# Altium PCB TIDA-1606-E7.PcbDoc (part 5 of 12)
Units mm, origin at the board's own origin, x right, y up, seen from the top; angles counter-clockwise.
Board outline 270 x 345 mm, 4 copper layers (Top Layer, Signal Layer 1, Signal Layer 2, Bottom Layer), stack 2.326 mm thick; 1282 components, 576 nets, 3628 pads, 4132 vias.
Unrouted connection lines stored in the file: 1719.
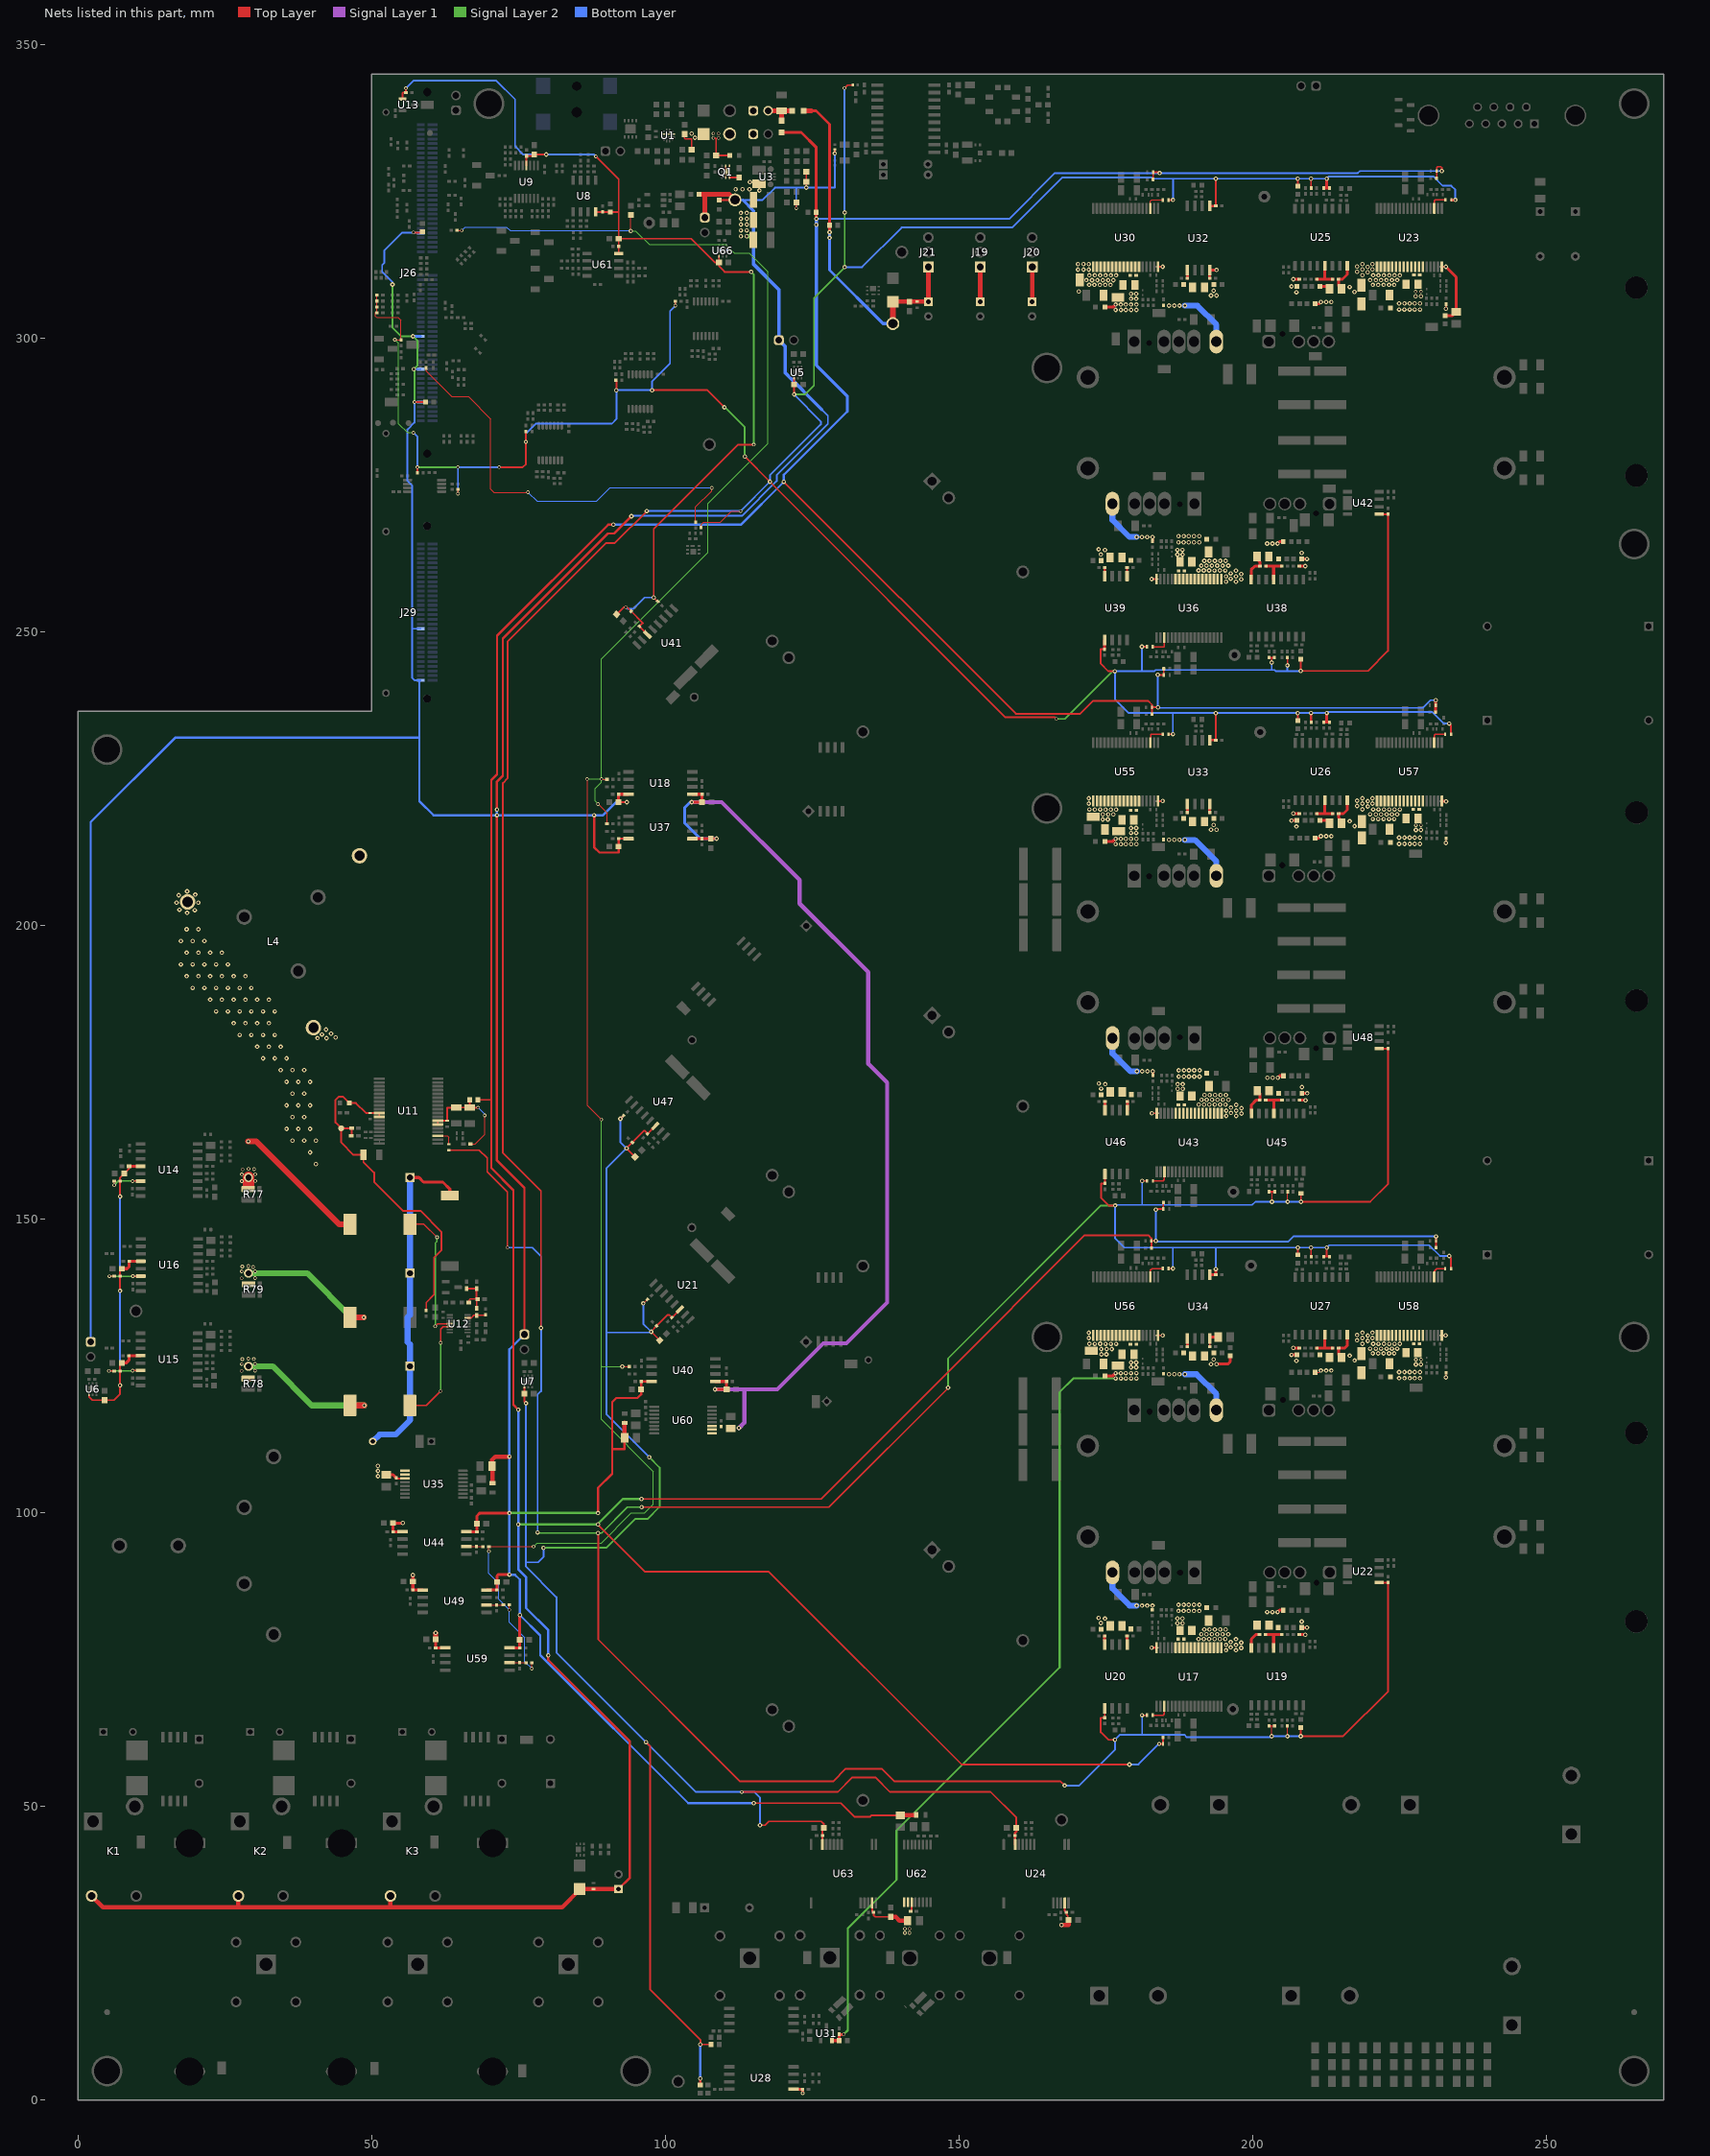
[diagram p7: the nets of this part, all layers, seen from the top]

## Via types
v1: diameter 0.762, hole 0.356, Top Layer to Bottom Layer, tented both sides, 2905 vias
v2: diameter 0.61, hole 0.356, Top Layer to Bottom Layer, tented both sides, 1212 vias
v3: diameter 0.864, hole 0.406, Top Layer to Bottom Layer, tented both sides, 15 vias

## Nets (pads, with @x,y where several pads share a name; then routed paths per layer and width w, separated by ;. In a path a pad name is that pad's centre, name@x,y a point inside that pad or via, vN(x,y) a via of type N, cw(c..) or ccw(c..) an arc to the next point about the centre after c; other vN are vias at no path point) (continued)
3.3VREF: R17.1 R65.2 R70.2 R75.2 R207.2 R225.2 R300.2 R304.1 | length 359
  Top Layer w0.203: R304.1@64.571,318.403 v2(65.368,318.403) ; v2(70,93.495) R207.2@70,94.3 v2(77.6,94.3) ; R225.2@73.456,84.356 73.478,84.334 v2(73.478,83.534) ; v2(77.31,73.525) R300.2@77.31,74.525 ; v2(86.702,225) 86.702,169.439 v2(89.138,167.004) ; v2(88.6,220.739) 90.1,219.239 R70.2@90.1,217.374 ; v2(89.154,225) 89.215,224.939 R65.2@90.1,224.939 ; v1(92.709,124.943) R75.2@93.88,124.943 ; v1(94.16,318.3) R17.1@94.16,321.02
  Signal Layer 2 w0.203: v2(77.6,94.3) 78.2,94.9 89.15,94.9 94.25,100 96.478,100 97.989,101.511 97.989,107.077 89.138,115.928 89.138,125 ; v2(86.702,225) v2(89.154,225) ; v2(88.6,220.739) 88.102,221.236 88.102,223.367 89.154,224.418 v2(89.154,225) ; v2(89.138,167.004) 89.138,125 ; v1(92.709,124.943) 89.195,124.943 89.138,125 ; v1(94.16,318.3) 94.995,318.3 97.295,316 110.339,316 111.817,314.522 114.36,314.522 117.484,311.398 117.484,282.1 107.3,271.916 107.3,263.612 89.154,245.466 v2(89.154,225)
  Bottom Layer w0.203: v2(65.368,318.403) 65.965,319 73.006,319 73.603,318.403 94.057,318.403 v1(94.16,318.3) ; v2(70,93.495) 70,89.721 71.681,88.04 71.681,85.331 v2(73.478,83.534) 73.478,81.383 76.1,78.761 76.1,74.735 v2(77.31,73.525)
12V_FET_DRAIN: Q1.1 Q1.2 Q1.5 Q1.6 Q1.8 R7.1 | length 5.5
  Top Layer w0.254: Q1.5@110.329,327.42 Q1.2@110.329,329.37 ; Q1.8@110.646,328.386 Q1.8@110.654,328.395 ; Q1.6@110.979,327.42 Q1.1@110.979,329.37
  Top Layer w0.305: Q1.6@110.979,327.42 R7.1@112.602,327.42
+3V3: C19.1 C157.2 C159.1 C170.2 C246.1 C253.1 C260.1 C303.1 C315.2 C318.1 FB17.1 R104.1 R148.2 R159.2 R160.2 R161.2 R162.2 R187.2 R198.2 R199.2 R200.2 R201.2 R213.2 R214.2 R215.2 R216.2 R228.2 R229.2 R230.2 R231.2 R249.2 R267.2 R278.2 R287.1 R289.2 R290.2 R291.2 R292.2 R317.2 R328.2 R329.2 R330.2 R331.2 R374.2 R380.2 R388.2 R412.2 R433.2 R436.2 R438.2 R439.2 R440.2 R461.2 R508.2 R528.2 R536.2 U5.1 U20.1 U22.1 U32.1 U33.1 U34.1 U39.1 U42.1 U46.1 U48.1 | length 1375.9
  Top Layer w0.203: R440.2@50.722,304.385 50.722,303.784 50.906,303.6 54.54,303.6 55.019,303.121 R374.2@55.019,299.789 v2(53.998,299.789) ; R440.2@50.943,304.385 R439.2@50.943,305.385 R438.2@50.943,306.385 R436.2@50.943,307.385 ; R433.2@106.123,267.835 106.123,268.297 106.546,268.721 109.419,268.721 111.318,270.62 v2(112.851,270.62) ; v1(203.297,62) 203.297,63.736 R160.2@203.772,63.736 ; v1(203.336,153.002) 203.336,154.732 ; v1(205.958,62) R161.2@205.958,63.736 ; v1(205.997,153.002) R330.2@205.997,154.732
  Top Layer w0.229: R104.1@63.181,161.798 68.367,161.798 69.715,160.45 69.715,158.099 73.152,154.662 v2(73.152,145.202) ; v1(181.202,65.574) R148.2@182.022,65.574 ; v1(181.242,156.57) R317.2@182.062,156.57 ; R508.2@185.733,141.635 v1(186.482,141.635) ; R267.2@185.733,232.63 v1(186.482,232.63) ; R289.2@202.82,245.698 203.295,245.698 ; R159.2@202.822,63.736 203.297,63.736 ; v1(203.295,244.814) 203.295,245.698 ; R290.2@203.77,245.698 203.295,245.698 ; v1(205.956,244.34) R291.2@205.956,245.698
  Top Layer w0.305: R287.1@57.837,277.148 v2(57.837,278.102) ; v2(64.737,273.578) R461.2@64.737,274.348 ; v2(71.759,278.102) 75.766,278.102 76.302,278.638 v2(76.302,282.4) 76.302,284.16 R412.2@76.315,284.173 ; v1(78.856,131.515) 78.856,154.824 72.376,161.304 72.376,224.294 73.177,225.095 73.177,248.407 89.946,265.176 91.44,265.176 v1(96.884,270.62) ; v1(88.6,96.6) 88.6,78.5 112.795,54.305 128.605,54.305 130.757,56.457 136.887,56.457 139.039,54.305 157.941,54.305 157.947,54.3 167.34,54.3 v1(168.04,53.6) ; R380.2@91.606,292.913 91.706,292.813 v1(91.706,291.2) ; v1(96,101) 127.9,101 148.185,121.285 v1(148.185,121.341) ; v1(97.79,291.2) 107.193,291.2 v1(110.093,288.3) ; v2(101.746,305.6) R388.2@101.746,306.331 ; v1(113.573,279.908) v1(117.856,275.625) 157.977,235.503 166.328,235.503 v2(166.6,235.231) ; U5.1@121.938,293.243 C19.1@121.938,292.171 121.938,290.513 121.948,290.502 v1(121.974,290.502) ; v2(130.556,342.644) 131.066,343.154 FB17.1@131.989,343.154 ; C303.1@174.851,247.1 174.178,247.1 174.178,244.632 175.471,243.339 v1(176.585,243.339) ; U20.1@174.859,66.715 174.859,65.149 C159.1@174.861,65.147 174.188,65.147 174.188,62.679 175.481,61.386 v1(176.595,61.386) ; U46.1@174.893,157.704 U46.1@174.899,157.71 174.899,156.14 C318.1@174.893,156.134 174.22,156.134 174.22,153.666 175.513,152.373 v1(176.627,152.373) ; v1(181.2,247.536) R278.2@182.02,247.536 ; R249.2@185.731,323.598 v1(186.48,323.598) ; R328.2@202.861,154.732 203.336,154.732 R329.2@203.811,154.732 ; R201.2@207.72,325.932 v1(207.72,327.211) ; R231.2@207.722,143.969 207.725,143.971 v1(207.725,145.202) ; R216.2@207.722,234.964 v1(207.722,236.222) ; R292.2@208.228,245.398 v1(208.228,243.4) 219.676,243.4 223.09,246.814 223.09,270.09 U42.1@221.6,270.09 ; R162.2@208.23,63.436 v1(208.23,62) 215.462,62 223.117,69.656 C157.2@223.117,88.168 U22.1@221.6,88.168 ; R331.2@208.269,154.432 v1(208.269,153.002) 220.049,153.002 223.117,156.07 C315.2@223.117,179.1 223.106,179.089 U48.1@221.6,179.089 ; R200.2@209.992,325.632 v1@209.992,327.099 ; R230.2@209.994,143.669 v1(209.994,145.202) ; R229.2@212.18,143.669 212.7,143.669 ; v1(212.655,145.202) 212.655,143.713 212.7,143.669 ; R228.2@213.13,143.669 212.7,143.669 ; v1(233.5,143.771) 233.825,143.446 R536.2@233.825,141.605 ; v1(233.512,234.428) 233.825,234.115 R528.2@233.825,232.6
  Top Layer w0.4: U32.1@192.735,322.568 C246.1@193.764,322.568 v1(193.764,327.211) ; U33.1@192.737,231.6 C253.1@193.766,231.6 v1(193.766,236.201) ; v1(209.992,236.235) 209.992,234.666 R215.2@209.994,234.664 ; R214.2@212.18,234.664 212.642,234.664 ; 212.642,325.632 212.653,325.643 ; 212.655,234.678 212.642,234.664 ; R213.2@213.13,234.664 212.642,234.664
  Top Layer w0.5: U39.1@174.849,248.668 174.849,247.102 C303.1@174.851,247.1 ; U34.1@192.737,140.605 C260.1@193.766,140.605 193.766,141.544 v1(193.774,141.552) ; R199.2@212.178,325.632 212.642,325.632 R198.2@213.128,325.632 ; R187.2@233.873,323.605 v1(234.548,323.605)
  Top Layer w0.508: 212.653,325.643 v1(212.653,327.211) ; 212.655,234.678 v1(212.655,236.235)
  Signal Layer 2 w0.203: v2(53.998,299.789) 54.632,299.155 54.632,285.496 56.156,283.972 v2(57.137,283.972)
  Signal Layer 2 w0.305: v2(57.837,278.102) v2(64.737,278.102) ; v1(78.304,96.7) 78.404,96.6 v1(88.6,96.6) 89.2,96.6 93.6,101 v1(96,101) ; v1(110.093,288.3) 110.156,288.3 113.573,284.884 v1(113.573,279.908) ; v1(121.974,290.502) 123.852,290.502 125.349,291.998 125.349,306.899 130.581,312.132 v1(130.581,321.462) ; v1(148.185,121.341) 148.185,126.333 174.225,152.373 v1(176.627,152.373) ; v2(166.6,235.231) 168.041,235.231 176.148,243.339 v1(176.585,243.339)
  Bottom Layer w0.229: v2(73.152,145.202) 77.385,145.202 78.856,143.732 v1(78.856,131.515) ; 181.202,62.254 v1(181.202,65.574) ; 181.242,152.467 v1(181.242,156.57) ; 186.454,236.235 186.482,236.207 v1(186.482,232.63) ; v1(186.482,141.635) 186.482,145.184 186.5,145.202 ; 205.956,243.383 206,243.339
  Bottom Layer w0.305: v2(57.137,283.972) 57.837,283.272 v2(57.837,278.102) ; v2(64.737,273.578) v2(64.737,278.102) v2(71.759,278.102) ; v2(76.302,282.4) 76.302,283.812 77.986,285.496 90.916,285.496 91.706,286.286 v1(91.706,291.2) v1(97.79,291.2) 97.79,292.743 100.845,295.798 100.845,304.699 v2(101.746,305.6) ; v1(78.304,96.7) 78.304,120.168 78.9,120.764 78.9,131.471 v1(78.856,131.515) ; v1(96.884,270.62) v2(112.851,270.62) v1(117.856,275.625) 117.856,276.707 126.512,285.363 126.512,285.888 121.974,290.426 v1(121.974,290.502) ; v2(130.556,342.644) 130.556,321.488 v1(130.581,321.462) ; v1(130.581,312.166) 133.533,312.166 140.264,318.897 159.086,318.897 167.596,327.406 173.395,327.406 173.655,327.406 ; v1(168.04,53.6) 170.499,53.6 176.595,59.696 v1(176.595,61.386) 177.464,62.254 181.202,62.254 188.382,62.254 188.808,61.828 203.125,61.828 v1(203.297,62) v1(205.958,62) v1(208.23,62) ; 173.655,327.406 174.265,327.406 174.538,327.406 175.148,327.406 175.43,327.406 176.04,327.406 176.312,327.406 182.817,327.406 183.012,327.211 186.48,327.211 ; v1(181.2,247.536) 181.2,243.341 181.202,243.339 ; v1(186.48,323.598) 186.48,327.211 ; v1(193.774,141.552) 193.774,145.202 ; v1(203.295,244.814) 203.295,243.557 ; 205.956,243.383 v1(205.956,244.34) ; v1(208.228,243.4) 208.166,243.339 206,243.339 204.013,243.339 203.795,243.557 203.295,243.557 ; v1(208.269,153.002) v1(205.997,153.002) v1(203.336,153.002) 200.506,153.002 199.971,152.467 184.948,152.467 184.944,152.47 184.334,152.47 184.331,152.467 181.242,152.467 176.721,152.467 v1(176.627,152.373) 176.627,146.75 178.175,145.202 186.5,145.202 193.774,145.202 ; v1(233.5,143.771) 231.932,143.771 230.096,145.608 213.061,145.608 v1(212.655,145.202) v1(209.994,145.202) v1(207.725,145.202) 193.774,145.202 ; v1(233.512,234.428) 232.605,234.428 230.597,236.435 212.856,236.435 v1(212.655,236.235) v1(209.992,236.235) 186.454,236.235 178.957,236.235 176.585,238.606 v1(176.585,243.339) 181.202,243.339 ; v1(234.548,323.605) 234.548,325.342 233.865,326.025 232.411,326.025 230.85,327.585 213.028,327.585 v1(212.653,327.211) v1(209.992,327.211) v1(207.72,327.211) v1(193.764,327.211) 186.48,327.211 ; 181.202,243.339 183.293,243.339 183.515,243.561 184.125,243.561 184.129,243.557 203.295,243.557
+3V3_Ua: C27.1 C28.2 C29.1 C166.1 C328.1 C409.2 C443.1 L7.2 L8.1 R177.1 R178.1 R183.1 R339.1 R340.1 R352.1 U7.1 U21.8 U24.14 U47.8 U63.14 | length 363.4
  Top Layer w0.203: v1(96.293,135.7) 96.338,135.7 R178.1@96.986,136.347
  Top Layer w0.256: v1(92.375,167.131) R340.1@92.893,167.649
  Top Layer w0.305: U7.1@76.04,121.426 C27.1@76.04,120.318 76.04,118.965 v1(76.31,118.695) ; R352.1@94.897,160.654 v1(93.444,162.106) 96.438,165.1 96.486,165.1 C328.1@97,164.586 98.33,165.916 U47.8@98.335,165.916 ; v1(96.769,61) 97.437,60.332 97.437,18.868 106,10.305 v1(106,9.5) L8.1@107.837,9.5 ; R183.1@99.083,129.412 v1(97.631,130.864) 97.631,130.946 R177.1@98.549,131.864 100.385,133.7 100.759,133.7 C166.1@101.153,133.305 U21.8@102.522,134.674 ; v2(113.067,52.5) 113.086,52.519 129.399,52.519 131.88,55 135.782,55 138.263,52.519 155.405,52.519 159.8,48.124 C28.2@159.8,46.387 ; v1(116.149,46.847) 117.049,46.847 117.699,47.497 126.612,47.497 126.998,47.11 C409.2@126.998,46.387 126.799,46.187 C443.1@126.799,45.1 U63.14@126.799,43.55
  Top Layer w0.381: L7.2@106,2.6 v1(106,3.7) ; U24.14@159.601,43.55 C29.1@159.601,45.1 159.601,45.587 159.8,45.787 C28.2@159.8,46.387
  Signal Layer 2 w0.305: v1(79.3,94.075) 89.978,94.075 94.903,99 97.013,99 99.083,101.07 99.083,107.729 v1(97.312,109.5)
  Bottom Layer w0.305: v1@76.31,118.89 v1(76.31,118.695) 76.31,91.6 ; v1(79.3,94.075) 79.3,92.5 78.4,91.6 76.31,91.6 ; v1(92.375,167.131) 92.375,163.176 v1(93.444,162.106) 90.002,158.664 90.002,130.75 ; v1(96.293,135.7) 96.293,132.202 v1(97.631,130.864) 97.517,130.75 90.002,130.75 ; v1(97.312,109.5) 97.312,109.519 90.002,116.828 90.002,130.75 ; v1(116.149,46.847) 116.149,51.587 115.236,52.5 v2(113.067,52.5) 105.269,52.5 v1(96.769,61) 81.502,76.267 81.502,85.676 76.31,90.868 76.31,91.6
  Bottom Layer w0.381: v1(106,3.7) v1(106,9.5)
+3V3_Ua2: C30.1 C31.1 C104.1 C180.1 C311.1 C312.1 C450.1 C451.1 C484.1 R307.1 R308.1 R312.1 U8.8 U9.4 U13.1 U41.8 U61.8 U66.1 | length 178.5
  Top Layer w0.256: v1(98.066,255.9) R308.1@98.759,255.207
  Top Layer w0.305: U13.1@55.294,340.762 55.294,341.784 55.423,341.912 C104.1@55.874,341.912 v2(55.874,342.64) ; U9.4@76.402,329.468 C180.1@76.402,331.092 ; C180.1@76.411,331.1 77.504,331.1 C311.1@77.734,331.33 v1(79.756,331.33) ; U8.8@88.157,321.554 C450.1@89.36,321.554 C451.1@90.66,321.554 92.092,321.554 ; v2(88.2,331.02) 92.092,327.127 92.092,321.554 ; R312.1@91.748,253.031 92.989,254.273 v2(93.322,254.273) 93.493,254.273 R307.1@94.2,253.565 96.216,251.549 C312.1@95.641,250.974 95.641,250.961 U41.8@97.01,249.593 ; U61.8@92.102,314.494 C30.1@92.102,315.698 C31.1@92.102,316.998 ; v1(98.066,255.9) 98.066,267.569 112.436,281.94 v2(115.1,281.94) ; U66.1@109.167,314.008 C484.1@109.167,312.942 ; v1(114.65,311.343) 110.141,311.343 109.167,312.316 C484.1@109.167,312.942 ; 92.092,321.554 92.092,317.008 C31.1@92.102,316.998 ; C31.1@92.102,316.998 104.466,316.998 108.522,312.942 C484.1@109.167,312.942
  Signal Layer 2 w0.305: v1(114.65,311.343) 114.65,311.307 115.1,310.858 v2(115.1,281.94)
  Bottom Layer w0.305: v2(55.874,342.64) 57.15,343.916 71.271,343.916 74.452,340.735 74.452,332.738 75.861,331.33 v1(79.756,331.33) 87.89,331.33 v2(88.2,331.02) ; v2(93.322,254.273) 93.594,254 94.635,254 96.535,255.9 v1(98.066,255.9)
+3V3_Ud: C24.1 C110.1 C112.2 C119.1 C121.2 C128.1 C130.2 R132.1 R137.1 R142.1 U6.1 U14.12 U15.12 U16.12 | length 64
  Top Layer w0.305: U6.1@1.9,120.137 1.9,119.767 2.449,119.217 C24.1@4.588,119.217 6.121,119.217 7.2,120.297 v1(7.2,121.742) R137.1@7.2,124.2 7.2,125.256 C119.1@7.476,125.532 ; v1(7.2,137.823) R142.1@7.2,140.35 7.2,141.287 C128.1@7.518,141.605 ; v1(7.2,153.9) R132.1@7.2,156.534 7.2,157.109 C110.1@7.9,157.809 8.712,158.621 C112.2@8.712,159.06
  Top Layer w0.5: C119.1@7.476,125.532 8.225,125.532 8.712,126.019 C121.2@8.712,126.802 U15.12@10.691,126.802 ; C128.1@7.518,141.605 8.388,141.605 8.754,141.971 C130.2@8.754,142.875 U16.12@10.733,142.875 ; C112.2@8.712,159.06 U14.12@10.691,159.06
  Bottom Layer w0.305: v1(7.2,121.742) v1(7.2,137.823) v1(7.2,153.9)
+5V: C8.1 C9.1 C10.1 C11.1 C34.1 C58.2 C59.1 C65.2 C66.1 C168.1 C211.2 C229.1 C283.2 C284.1 C322.2 C323.1 C355.2 C356.1 C360.1 C445.1 C449.1 D3.2 FB16.1 J10.1 J11.1 J12.1 J26.9 J26.23 J26.37 J26.73 J29.1 J29.23 J31.1 L11.2 L12.2 L14.2 R12.2 R16.2 R35.2 TP3.1 U3.3 U18.8 U37.8 U40.8 U44.8 U49.8 U59.8 | length 820.1
  Top Layer w0.305: v2(57.137,318.052) 58.554,318.052 C168.1@58.702,318.2 ; v2(57.317,289.185) 57.331,289.2 C34.1@59.234,289.2 ; C59.1@92.078,221.062 93.478,221.062 v1(93.481,221.065) ; D3.2@109.193,323.585 111.883,323.585 TP3.1@111.902,323.605 ; v1(115.1,50.6) 129.897,50.6 132.222,48.276 134.932,48.276 135.189,48.532 C360.1@140.042,48.532 ; v2(122.337,322.165) R16.2@122.337,323.184 ; v1(124.045,325.7) C8.1@124.045,326.679 R12.2@124.045,328.417 ; v1(128.88,331.521) FB16.1@128.88,332.203 ; L11.2@142.674,48.532 L11.2@142.742,48.6
  Top Layer w0.381: v1(71.374,218.834) 71.374,160.02 76.04,155.354 J12.1@76.04,130.412 ; v1(71.374,219.786) 71.374,224.561 72.376,225.564 72.376,248.932 90.245,266.8 91.327,266.8 v1(94.275,269.748) ; v1(87.911,218.834) 87.911,213.391 88.819,212.483 92.078,212.483 C66.1@92.078,213.5 C65.2@92.078,214.834 U37.8@93.75,214.834 ; v1(88.6,100) 88.6,104.292 91,106.692 91,118.898 91.702,119.6 95.302,119.6 95.93,120.228 C356.1@95.93,121.043 C355.2@95.93,122.412 U40.8@97.693,122.412 ; 91.152,110.902 93.105,110.902 C445.1@93.105,112.793 C445.1@93.1,112.798
  Top Layer w0.5: U44.8@66.187,96.83 C211.2@67.95,96.83 C229.1@67.95,98.2 67.95,99.478 68.472,100 v1(73.5,100) ; U49.8@69.613,86.896 C283.2@71.376,86.896 C284.1@71.376,88.266 71.376,89.302 71.576,89.502 v1(73.5,89.502) ; U59.8@73.497,77.056 C322.2@75.26,77.056 C323.1@75.26,78.425 v1(75.26,82.635) ; C59.1@92.078,221.062 C58.2@92.078,222.4 C58.2@92.078,222.4 U18.8@93.75,222.399
  Top Layer w0.7: C449.1@70.605,107.932 C449.1@70.537,108 70.537,109.041 71.098,109.602 v1(73.5,109.602)
  Top Layer w0.762: L14.2@70.605,105.11 C449.1@70.605,107.932 ; C445.1@93.1,112.798 L12.2@93.1,115.358 ; R35.2@105.791,324.559 106.702,324.559 ; J31.1@106.767,320.6 106.767,324.494 106.702,324.559 ; TP3.1@111.902,323.605 110.948,324.559 106.702,324.559 ; C360.1@140.042,48.532 L11.2@142.674,48.532
  Signal Layer 2 w0.305: v1(53.59,309.201) 53.59,301.798 55.002,300.385 v1(57.074,300.385) 57.81,299.649 57.81,295.379 v1(57.217,294.785) 57.317,294.685 v2(57.317,289.185)
  Signal Layer 2 w0.381: v1@73.5,100 v1(88.6,100)
  Signal Layer 2 w0.762: v1(113.922,317.403) 114.617,317.403
  Bottom Layer w0.305: v1(53.59,309.201) 53.59,309.564 51.816,311.338 51.816,312.529 52.215,312.928 52.215,315.025 55.242,318.052 v2(57.137,318.052) 58.335,318.052 J26.73@58.402,317.985 ; 56.9,250.585 J29.23@58.402,250.585 ; v1(57.217,294.785) J26.23@58.402,294.785 ; J29.1@58.402,241.785 57.356,241.785 56.902,242.239 56.902,250.585 56.902,274.998 56.134,275.767 56.134,284.502 57.317,285.685 v2(57.317,289.185) J26.9@58.402,289.185 ; v1(94.275,269.748) 94.34,269.813 113.1,269.813 119,275.712 119,276.734 127.711,285.445 127.711,286.893 126.67,287.934 ; TP3.1@111.902,323.605 113.229,323.605 116.607,323.605 118.702,325.7 122.532,325.7 ; v2(122.337,322.165) 122.337,325.505 122.532,325.7 ; v1(128.88,331.521) 128.88,325.73 128.85,325.7 v1(124.045,325.7) 122.532,325.7
  Bottom Layer w0.381: J11.1@2.2,129.14 2.2,217.652 16.567,232.02 58.166,232.02 ; J29.1@58.166,241.757 58.166,232.02 ; v1(71.374,219.786) v1(71.374,218.834) ; 73.5,99.5 v1(73.5,109.602) 73.5,127.872 J12.1@76.04,130.412 ; v1(73.5,100) v1(73.5,89.502) 74.433,89.502 75.26,88.675 v1(75.26,82.635) 78.748,79.147 78.748,75.813 103.961,50.6 v1(115.1,50.6) ; v1(93.481,221.065) 91.657,221.065 89.426,218.834 v1(87.911,218.834) v1(71.374,218.834) ; 58.166,232.02 58.166,221.234 60.566,218.834 v1(71.374,218.834)
  Bottom Layer w0.5: v1(57.074,300.385) J26.37@58.402,300.385
  Bottom Layer w0.508: 113.229,323.605 115.077,321.756
  Bottom Layer w0.6: 115.077,321.756 115.077,312.623 119.38,308.32 J10.1@119.38,299.72 120.447,298.653 120.447,294.157 126.67,287.934
  other v1: 112.915,317.403 112.915,318.407 113.922,318.407 112.915,319.403 113.922,319.403 112.915,320.403 113.922,320.403 112.915,321.4 113.922,321.4 116.056,325.21 112.017,325.416 113.184,325.416 114.351,325.416 114.43,326.649
+5VISO_DC-: C176.2 C177.1 C222.1 C286.1 C446.1 C456.2 C457.1 U24.5 U28.1 U62.9 U62.10 U62.11 U63.5 | length 17.4
  Top Layer w0.254: C286.1@141.801,32.2 141.977,32.376 U62.11@141.977,33.705
  Top Layer w0.305: U63.5@135.249,33.6 135.249,32.25 C457.1@135.498,32 135.498,31.503 135.77,31.232 138.429,31.232 C456.2@138.432,31.235 ; U24.5@168.05,33.6 168.05,32.25 C177.1@168.3,32 ; C177.1@168.338,32 168.338,31.628 168.575,31.391 168.575,30.825 C176.2@168.701,30.7
  Top Layer w0.5: U28.1@121.85,1.887 121.863,1.9 C222.1@123.413,1.9 v2(123.413,1.2)
  Top Layer w0.762: C456.2@138.432,31.235 138.435,31.232 139.274,31.232 139.906,30.6 C446.1@141.285,30.6 ; v1(167.5,29.852) 168.701,29.852 C176.2@168.701,30.7
  other v2: 140.82,28.511 141.6,28.511 140.82,29.21 141.6,29.21
+5VISO_PCC: C198.1 C210.2 C268.1 C281.2 C295.1 C305.1 C308.2 C447.1 U35.9 U35.10 U35.11 U44.1 U49.1 U59.1 | length 16.6
  Top Layer w0.305: C447.1@54.2,106 54.325,105.875 U35.11@55.71,105.875
  Top Layer w0.5: C295.1@52.524,106.516 53.684,106.516 C447.1@54.2,106 ; U44.1@55.287,96.83 C308.2@53.684,96.83 C305.1@53.684,98.3 v1(55.346,98.3) ; C198.1@57.052,88.35 C210.2@57.051,86.9 57.055,86.896 U49.1@58.713,86.896 ; C198.1@57.052,88.35 v1(57.052,89.438) ; C268.1@60.935,78.51 C281.2@60.935,77.06 60.938,77.056 U59.1@62.597,77.056
  Top Layer w0.75: C268.1@60.935,78.51 v1(60.935,79.597)
  other v1: 51.117,106.279 51.117,107.175 51.102,108.017
+5VISO_SN: C56.1 C57.2 C63.1 C64.2 C353.1 C354.2 C361.1 C362.1 U18.1 U37.1 U40.1 U60.9 U60.10 U60.11 | length 169.2
  Top Layer w0.5: v1(104.539,221.062) 104.542,221.065 106.3,221.065 C57.2@106.3,222.399 U18.1@104.65,222.399 ; U37.1@104.65,214.834 C64.2@106.3,214.834 107.771,214.834 C63.1@107.773,214.837 v1(108.763,214.837) ; v1(108.5,121.065) C353.1@110.476,121.065 C354.2@110.476,122.41 U40.1@108.593,122.41
  Signal Layer 1 w0.7: v1(104.539,221.062) 109.633,221.062 122.9,207.794 122.9,203.782 134.6,192.082 134.6,176.5 137.8,173.3 137.8,135.833 130.867,128.9 126.928,128.9 119.093,121.065 113.5,121.065 ; v1(108.5,121.065) 113.5,121.065 ; v1(112.552,114.496) 112.596,114.496 113.5,115.4 113.5,121.065
  Bottom Layer w0.5: v1(104.539,221.062) 104.262,221.062 103.339,220.139 103.339,217.505 106.006,214.837 v1(108.763,214.837)
+12V: C94.1 C365.1 C431.1 C432.1 C433.1 C434.1 C435.1 C436.1 C437.1 C438.1 C439.1 C442.1 D5.1 FB10.1 FB11.1 FB12.1 FB13.1 FB14.1 FB15.1 FB21.1 FB22.1 FB23.1 FB25.2 K1.2 K2.2 K3.2 R36.2 | length 1012.6
  Top Layer w0.305: R36.2@68.121,170.359 70.325,170.359 70.4,170.434 ; v1@88.527,98.072 96.6,90 117.657,90 150.471,57.186 v1(179.07,57.186) ; v1(95.989,102.4) 126.555,102.4 146.837,122.682 146.837,122.686 171.451,147.3 182.275,147.3 182.804,146.771 C436.1@182.804,146.355 ; v1(120.212,275.6) 159.713,236.099 170.699,236.099 172.903,238.303 182.24,238.303 182.905,237.637 C435.1@182.905,237.2 ; FB15.1@182.797,145.11 182.804,145.117 C436.1@182.804,146.355 ; FB14.1@182.904,236.042 182.905,236.044 C435.1@182.905,237.2 ; FB13.1@183.098,327.1 C434.1@183.098,328.303 184.065,328.303 v1(184.201,328.168) ; v1(183.566,146.355) C436.1@182.804,146.355 ; v1(183.566,151.663) 183.693,151.79 C439.1@184.828,151.79 FB23.1@184.828,152.857 ; v1(183.896,242.748) 183.947,242.697 C438.1@184.903,242.697 FB22.1@184.903,243.764 ; v1(183.915,237.2) C435.1@182.905,237.2 ; v2(184.125,60.706) C437.1@184.792,60.706 184.792,61.783 FB21.1@184.797,61.788 ; FB12.1@231.257,145.205 C433.1@231.257,146.329 v1(231.257,147.107) ; FB10.1@231.378,327.304 C431.1@231.378,328.524 231.378,329.104 231.534,329.26 232.067,329.26 232.256,329.071 v1(232.256,328.531)
  Top Layer w0.381: v1(75,117.6) 74.168,118.432 74.168,154.982 70.4,158.75 70.4,170.434 70.4,172.476 70.4,224.815 71.4,225.815 71.4,249.397 90.329,268.326 v1(91.212,268.326) ; v1(80.115,75.75) 80.115,74.957 93.996,61.076 93.996,37.9 C365.1@92.078,35.982
  Top Layer w0.5: FB25.2@119.837,335.1 123.184,335.1 125.74,332.544 C442.1@125.74,321.485 125.74,320.392 v1(125.747,320.385) ; FB11.1@231.216,236.372 C432.1@231.216,237.541 231.216,238.397 v1(231.224,238.404)
  Top Layer w0.75: K1.2@2.35,34.797 4.254,32.893 53.235,32.893 ; 27.349,33.247 K2.2@27.349,34.797 ; K3.2@53.235,34.797 53.235,32.893 ; C365.1@92.078,35.982 C94.1@87.8,35.982 D5.1@85.446,35.982 85.446,35.846 82.493,32.893 53.235,32.893
  Signal Layer 2 w0.381: v1(75,98.072) 88.472,98.072 92.8,102.4 v1(95.989,102.4)
  Bottom Layer w0.305: v1(125.747,320.385) 158.587,320.385 166.37,328.168 v1(184.201,328.168) 217.932,328.168 218.295,328.531 v1(232.256,328.531) ; v1(179.07,57.186) 180.605,57.186 v2(184.125,60.706) ; v1(183.566,151.663) v1(183.566,146.355) 183.72,146.201 206.063,146.201 206.969,147.107 v1(231.257,147.107) ; v1(183.896,242.748) 183.896,237.219 v1(183.915,237.2) 184.015,237.1 229.048,237.1 230.353,238.404 v1(231.224,238.404)
  Bottom Layer w0.381: v1(75,117.6) v1(75,98.072) 75,90.43 76.314,89.117 76.314,83.846 80.115,80.044 v1(80.115,75.75) ; v1(91.212,268.326) 91.246,268.291 112.903,268.291 v1(120.212,275.6) 120.212,276.785 130.997,287.57
  Bottom Layer w0.5: v1(125.747,320.385) 125.755,320.377 125.755,295.453 130.997,290.211 130.997,287.57
  Bottom Layer w0.508: C365.1@92.078,35.982 C365.1@92.096,36
  other v1: 88.6,98.072 125.738,319.369
+12V_AEF: C85.1 C86.1 C87.1 R36.1 R109.2 U11.6 U11.7 | length 19.2
  Top Layer w0.203: R109.2@66.854,162.857 67.689,162.857 69.288,164.456 v2(69.288,167.712)
  Top Layer w0.305: U11.6@61.293,166.171 61.293,166.807 U11.7@61.3,166.814 ; U11.7@61.293,166.821 U11.7@61.3,166.814 ; R36.1@66.721,170.359 66.721,169.045 C85.1@64.446,169.045 64.417,169.016 62.888,169.016 C87.1@62.888,166.814 U11.7@61.3,166.814 ; C86.1@66.732,169.034 v2(68.173,169.034)
  Bottom Layer w0.203: v2(68.173,169.034) 69.288,167.919 v2(69.288,167.712)
+12V_AEF_ISO: C89.1 C90.1 D4.2 R38.2 R39.2 R71.2 TP6.1 U11.28 U11.29 | length 59.7
  Top Layer w0.305: R39.2@46.574,164.221 46.609,164.256 R38.2@46.609,165.521 TP6.1@44.856,165.521 ; U11.29@51.343,167.471 U11.28@51.343,168.121 C89.1@49.784,168.121 49.058,168.121 47.363,169.816 D4.2@46.235,169.816 45.151,170.901 44.384,170.901 44.384,170.869 43.879,170.364 43.879,166.498 TP6.1@44.856,165.521 ; R71.2@59.333,134.493 59.333,135.845 60.65,137.162 60.65,143.471 61.902,144.724 61.902,147.896 58.328,151.47 55.364,151.47 50.467,156.367 50.467,157.961 48.65,159.779 C90.1@48.65,161 46.956,161 44.856,163.1 TP6.1@44.856,165.521
+12V_FAN: C366.1 C367.1 C368.1 C369.1 C401.1 C440.1 D6.1 FB24.2 J19.1 J20.1 J21.1 TP63.1 | length 72.3
  Top Layer w0.5: 124.968,338.78 125.71,338.78 128,336.49 C440.1@128,319.287 v1(128,318.102)
  Top Layer w0.762: FB24.2@123.615,338.78 124.968,338.78 ; D6.1@138.8,306.28 138.805,306.275 C401.1@141.6,306.275 C369.1@142.932,306.275 C368.1@144.822,306.275 144.825,309.22 J21.1@144.829,312.2 ; C367.1@153.662,306.278 J19.1@153.662,312.2 ; C366.1@162.495,306.275 J20.1@162.495,312.2
  Top Layer w0.8: 144.8,309.245 144.825,309.22
  Top Layer w1: TP63.1@138.786,302.539 138.8,302.554 D6.1@138.8,306.28
  Bottom Layer w0.5: v1(128,318.102) 128,311.656 137.116,302.539 TP63.1@138.786,302.539
  other v1: 128,317.144
+12V_JP: C441.1 FB24.1 FB25.1 J2.2 | length 5.8
  Top Layer w0.381: J2.2@117.542,338.8 J2.2@117.547,338.805
  Top Layer w0.8: J2.2@117.542,338.8 117.563,338.78 C441.1@119.837,338.78 ; FB25.1@119.837,337.1 C441.1@119.837,338.78 ; FB24.1@121.615,338.78 C441.1@119.837,338.78
+12V_OUT: C3.1 D1.2 D2.1 J2.1 J8.1 R2.2 R6.2 TP1.1 U1.6 | length 9.5
  Top Layer w0.254: C3.1@103.327,334.81 103.327,334.06 103.397,333.99 104.525,333.99 R2.2@104.525,332.147 ; D2.1@106.551,334.813 D2.1@106.564,334.8
  Top Layer w0.305: v2(108.21,334.158) 108.521,334.158 108.685,333.994 R6.2@108.685,331.17 D1.2@111.002,331.17
  Top Layer w1.016: TP1.1@110.994,334.8 TP1.1@111.002,334.809
  other v1: 105.08,334.188 104.525,334.899
  other v2: 109.083,334.158 108.21,334.9 109.083,334.9
+15V_MID1: C201.1 C238.2 C247.2 C248.1 C251.1 D28.2 pad.1@193.853,299.48 R510.2 TP50.1 U30.28 U30.29 U32.5 | length 13
  Top Layer w0.5: D28.2@174.885,305.339 176.265,305.339 v1(176.71,305.784) ; C247.2@188.925,310.268 U32.5@188.925,311.668
  Bottom Layer w1: v1(188.488,305.599) 190.615,305.599 193.853,302.361 pad.1@193.853,299.48
  other v1: 176.71,304.884 177.609,304.884 178.445,304.884 179.344,304.884 180.258,304.884 185.791,305.599 186.688,305.599 187.581,305.599 177.596,305.784 178.445,305.784 179.331,305.784 180.245,305.784
+15V_MID2: C214.1 C254.2 C255.1 C258.1 C400.2 D29.2 pad.1@193.855,208.511 R530.2 TP51.1 U33.5 U55.28 U55.29 | length 12.7
  Top Layer w0.5: D29.2@174.887,214.371 176.267,214.371 v1(176.712,214.816) ; C254.2@188.927,219.3 U33.5@188.927,220.7
  Bottom Layer w1: v1(188.49,214.631) 190.194,214.631 193.855,210.97 pad.1@193.855,208.511
  other v1: 176.712,213.916 177.611,213.916 178.447,213.916 179.346,213.916 180.26,213.916 185.793,214.631 186.69,214.631 187.583,214.631 177.598,214.816 178.447,214.816 179.333,214.816 180.247,214.816
+15V_MID3: C235.2 C236.1 C239.1 C261.2 C262.1 C265.1 C408.2 D30.2 pad.1@193.855,117.516 R538.2 TP56.1 U31.2 U34.5 U56.28 U56.29 | length 151.2
  Top Layer w0.5: U31.2@128.412,10.206 128.462,10.157 C236.1@129.619,10.157 C235.2@129.619,11.257 129.659,11.217 v2(130.404,11.217) ; D30.2@174.887,123.376 176.267,123.376 v1(176.712,123.821) ; C261.2@188.927,128.305 U34.5@188.927,129.705
  Signal Layer 2 w0.35: v2(130.404,11.217) 131.1,11.912 131.1,29.264 139.392,37.556 139.392,45.919 167.171,73.697 167.171,120.599 169.493,122.921 v1(176.712,122.921)
  Bottom Layer w1: v1(188.49,123.636) 190.486,123.636 193.855,120.267 pad.1@193.855,117.516
  other v1: 177.611,122.921 178.447,122.921 179.346,122.921 180.26,122.921 185.793,123.636 186.69,123.636 187.583,123.636 177.598,123.821 178.447,123.821 179.333,123.821 180.247,123.821
+15V_SN_L1: C136.1 C139.2 C140.2 C141.1 C142.1 C282.2 C294.1 C296.1 C304.2 D32.2 pad.1@176.163,271.85 R173.2 R293.2 U36.28 U36.29 U38.5 U39.5 | length 16.4
  Top Layer w0.4: U39.5@178.659,259.568 C304.2@178.659,261.029 ; R173.2@182.99,265.498 v1@182.99,266.298
  Top Layer w0.5: C294.1@202.298,261.254 203.608,261.254 ; C139.2@202.811,262.884 C139.2@202.814,262.881 ; U38.5@203.608,258.972 203.608,261.254 ; v1(204.288,265.1) 204.604,265.416 R293.2@205.242,265.416 ; C296.1@204.989,261.254 203.608,261.254
  Bottom Layer w1: pad.1@176.163,271.85 176.163,269.099 179.062,266.2 v1(180.293,266.2)
  other v1: 202.518,265.1 203.4,265.1 187.418,265.3 188.304,265.3 189.153,265.3 190.039,265.3 190.953,265.3 181.2,266.2 182.093,266.2 182.99,266.2 187.415,266.348 188.314,266.348 189.15,266.348 190.049,266.348 190.963,266.348
+15V_SN_L2: C137.1 C164.2 C241.2 C279.1 C280.1 C325.2 C337.1 C339.1 C347.2 D33.2 pad.1@176.165,180.882 R319.2 R332.2 U43.28 U43.29 U45.5 U46.5 | length 16.4
  Top Layer w0.5: C347.2@178.701,170.063 178.709,170.055 U46.5@178.709,168.61 ; R319.2@183.031,174.532 v1(183.031,175.234) ; C337.1@202.255,170.288 203.8,170.288 ; U45.5@203.649,168.006 203.649,170.137 203.8,170.288 ; v1(204.329,174.134) 204.646,174.45 R332.2@205.283,174.45 ; C339.1@205.031,170.292 205.027,170.288 203.8,170.288
  Bottom Layer w1: pad.1@176.165,180.882 176.165,178.267 179.198,175.234 v1(180.334,175.234)
  other v1: 202.559,174.134 203.442,174.134 187.46,174.334 188.346,174.334 189.195,174.334 190.081,174.334 190.995,174.334 181.242,175.234 182.135,175.234 187.456,175.382 188.356,175.382 189.192,175.382 190.091,175.382 191.005,175.382
+15V_SN_L3: C135.1 C138.2 C148.2 C150.1 C151.2 C152.1 C153.1 C160.2 C161.1 D31.2 pad.1@176.165,89.887 R150.2 R163.2 U17.28 U17.29 U19.5 U20.5 | length 15.7
  Top Layer w0.5: C160.2@178.661,79.065 178.661,77.623 U20.5@178.669,77.615 ; C150.1@202.215,79.29 203.657,79.29 ; U19.5@203.61,77.011 203.61,79.242 203.657,79.29 ; v1(204.29,83.136) 204.606,83.452 R163.2@205.244,83.452 ; C152.1@204.991,79.29 203.657,79.29
  Bottom Layer w1: pad.1@176.165,89.887 176.165,87.173 179.102,84.236 v1(180.295,84.236)
  other v1: 202.52,83.136 203.402,83.136 187.42,83.336 188.306,83.336 189.155,83.336 190.041,83.336 190.955,83.336 181.202,84.236 182.095,84.236 182.992,84.236 187.417,84.385 188.316,84.385 189.152,84.385 190.051,84.385 190.965,84.385
+15V_VDC-1: C178.2 C179.1 C188.2 C190.1 C191.2 C192.1 D22.2 R190.2 R202.2 TP41.1 U23.28 U23.29 U25.5 | length 8.7
  Top Layer w0.229: v1(232.945,305.076) 233.002,305.133 R190.2@233.002,305.866
  Top Layer w0.4: R202.2@210.706,305.914 211.344,305.914 v1(211.66,306.23)
  Top Layer w0.5: C192.1@210.959,310.072 212.346,310.072 ; C191.2@211.498,308.895 212.688,308.895 C188.2@213.134,308.449 ; U25.5@212.34,312.358 212.34,310.078 212.346,310.072 ; C190.1@213.668,310.096 213.644,310.072 212.346,310.072
  other v1: 224.972,304.928 225.886,304.928 226.785,304.928 227.621,304.928 228.52,304.928 224.982,305.976 225.895,305.976 226.782,305.976 227.631,305.976 228.517,305.976 212.548,306.23 213.43,306.23
+15V_VDC-2: C182.1 C203.1 C204.2 C205.1 C206.2 C416.2 D23.2 R217.2 R252.2 TP42.1 U26.5 U57.28 U57.29 | length 8.7
  Top Layer w0.203: v1@233.004,214.165 R252.2@233.004,214.898
  Top Layer w0.5: R217.2@210.708,214.945 211.346,214.945 v1(211.662,215.262) ; C205.1@210.961,219.104 212.218,219.104 ; C206.2@211.5,217.927 212.69,217.927 C204.2@213.136,217.48 ; U26.5@212.342,221.39 212.342,219.228 212.218,219.104 ; C203.1@213.67,219.127 213.646,219.104 212.218,219.104
  other v1: 224.974,213.959 225.888,213.959 226.787,213.959 227.623,213.959 228.522,213.959 232.947,214.108 224.984,215.008 225.897,215.008 226.784,215.008 227.633,215.008 228.519,215.008 212.55,215.262 213.432,215.262
+15V_VDC-3: C193.1 C216.1 C217.2 C218.1 C219.2 C424.2 D24.2 R232.2 R281.2 TP47.1 U27.5 U58.28 U58.29 | length 6.9
  Top Layer w0.203: R232.2@210.708,123.95 211.346,123.95 v1(211.662,124.266) ; v1(232.947,123.112) 233.004,123.169 R281.2@233.004,123.902
  Top Layer w0.5: C218.1@210.961,128.109 212.458,128.109 ; U27.5@212.342,130.394 212.342,128.224 212.458,128.109 ; C216.1@213.67,128.109 212.458,128.109
  other v1: 224.974,122.964 225.888,122.964 226.787,122.964 227.623,122.964 228.522,122.964 224.984,124.012 225.897,124.012 226.784,124.012 227.633,124.012 228.519,124.012 212.55,124.266 213.432,124.266
-4V_MID1: C201.2 C238.1 C250.1 C251.2 C252.2 NT20.1 R568.1 TP54.1 U30.19 U30.20 U30.21 U30.22 U30.23 U30.24 U30.25 U30.26 U30.27 U30.30 U30.31 U30.36 U32.8 | length 3.3
  Top Layer w0.305: U30.36@183.928,312.215 v1(184.715,312.215)
  Top Layer w0.5: C250.1@192.735,310.269 U32.8@192.735,311.668 v1(193.885,311.668)
  other v1: 179.327,306.77 180.209,306.77 192.943,307.324 193.898,307.324 179.327,307.612 180.209,307.612 170.435,308.009 193.398,308.137 172.199,309.139 173.113,309.139 174.035,309.139 174.949,309.139 175.835,309.139 172.699,309.948 173.613,309.948 174.535,309.948 175.449,309.948 176.335,309.948 171.735,309.952 172.249,310.776 173.163,310.768 174.085,310.776 174.999,310.768 175.898,310.768 176.794,310.769 170.301,311.745 171.238,311.745 172.135,311.745 170.301,312.676 171.238,312.676 172.135,312.676
-4V_MID2: C214.2 C257.1 C258.2 C259.2 C400.1 NT23.1 R569.1 TP55.1 U33.8 U55.19 U55.20 U55.21 U55.22 U55.23 U55.24 U55.25 U55.26 U55.27 U55.30 U55.31 U55.36 | length 2.2
  Top Layer w0.305: U55.36@183.93,221.247 v1(184.717,221.247)
  Top Layer w0.5: C257.1@192.738,219.3 U33.8@192.738,220.699
  other v1: 179.329,215.802 180.211,215.802 192.945,216.356 193.9,216.356 179.329,216.644 180.211,216.644 193.4,217.169 174.505,218.103 175.391,218.103 174.537,218.98 175.451,218.98 176.337,218.98 173.165,219.8 175.001,219.8 175.9,219.8 176.796,219.801 172.251,219.807 174.087,219.807 172.137,220.807 172.137,221.707
-4V_MID3: C239.2 C242.2 C264.1 C265.2 C266.2 C408.1 NT24.1 R254.1 R570.1 TP58.1 U34.8 U56.19 U56.20 U56.21 U56.22 U56.23 U56.24 U56.25 U56.26 U56.27 U56.30 U56.31 U56.36 | length 7.3
  Top Layer w0.305: U56.36@183.93,130.251 v1(184.717,130.251) ; C264.1@192.737,128.306 U34.8@192.737,129.705 U34.8@192.975,129.943
  Top Layer w0.5: v1(193.9,125.361) 195.814,125.361 196.216,125.763 C242.2@196.216,126.8
  Top Layer w0.508: U34.8@192.975,129.943 R254.1@194.184,129.943
  other v1: 179.329,124.806 180.211,124.806 192.945,125.361 179.329,125.649 180.211,125.649 193.4,126.174 174.274,127.021 175.135,127.021 174.265,127.93 175.179,127.93 176.065,127.93 172.251,128.812 173.165,128.805 174.087,128.812 175.001,128.805 175.9,128.805 176.796,128.806 172.137,129.812 172.137,130.712
-4V_SN_L1: C136.2 C139.1 C142.2 C282.1 C291.2 C293.1 C294.2 C307.1 C309.2 NT21.1 R322.1 U36.19 U36.20 U36.21 U36.22 U36.23 U36.24 U36.25 U36.26 U36.27 U36.30 U36.31 U36.36 U38.8 U39.8 | length 9.5
  Top Layer w0.381: v1(182.836,259.035) U36.36@183.674,259.035
  Top Layer w0.4: U39.8@174.857,259.576 U39.8@174.849,259.568 174.849,261.021 C307.1@174.857,261.029
  Top Layer w0.5: U38.8@199.779,258.954 U38.8@199.798,258.972 199.798,260.614 200.438,261.254 C294.2@201.298,261.254 201.298,261.965 200.782,262.481 C139.1@200.782,262.881 ; C291.2@207.977,261.254 208.978,261.254 v1(208.998,261.234) ; C293.1@208.392,262.45 v1(209.298,262.45)
  other v1: 195.498,258.598 197.198,258.598 198.098,258.998 196.298,259.098 195.498,259.498 197.198,259.498 198.098,259.898 196.298,259.998 197.198,260.482 190.838,260.504 191.735,260.505 192.634,260.505 193.548,260.498 194.47,260.505 195.384,260.498 191.298,261.325 192.184,261.325 193.098,261.325 194.02,261.325 194.934,261.325 195.898,261.322 191.798,262.135 192.684,262.135 193.598,262.135 194.52,262.135 195.434,262.135 187.24,263.198 188.109,263.198 174.198,263.231 208.379,263.492 174.902,263.998 187.24,264.004 188.098,264.004 173.819,264.1
-4V_SN_L2: C137.2 C164.1 C280.2 C325.1 C334.2 C336.1 C337.2 C350.1 C352.2 NT22.1 R323.1 U43.19 U43.20 U43.21 U43.22 U43.23 U43.24 U43.25 U43.26 U43.27 U43.30 U43.31 U43.36 U45.8 U46.8 | length 9.3
  Top Layer w0.305: v1(182.877,168.069) U43.36@183.716,168.069
  Top Layer w0.5: C350.1@174.891,170.055 174.899,170.047 U46.8@174.899,168.61 ; U45.8@199.839,168.006 199.839,169.517 200.61,170.288 C337.2@201.255,170.288 201.255,171.484 C164.1@200.82,171.918 ; C334.2@208.018,170.288 209.02,170.288 v1(209.039,170.268) ; C336.1@208.434,171.484 v1(209.339,171.484)
  other v1: 195.539,167.632 197.239,167.632 198.139,168.032 196.339,168.132 195.539,168.532 197.239,168.532 198.139,168.932 196.339,169.032 190.88,169.538 193.589,169.532 195.426,169.532 197.239,169.516 191.776,169.539 192.675,169.539 194.512,169.539 191.339,170.359 192.225,170.359 193.139,170.359 194.062,170.359 194.976,170.359 195.939,170.356 191.839,171.169 192.725,171.169 193.639,171.169 194.562,171.169 195.476,171.169 187.282,172.232 188.151,172.232 174.239,172.265 208.421,172.526 174.944,173.032 187.282,173.038 188.14,173.038 173.861,173.134
-4V_SN_L3: C135.2 C138.1 C147.2 C148.1 C149.1 C150.2 C161.2 C163.1 C165.2 NT18.1 R318.1 U17.19 U17.20 U17.21 U17.22 U17.23 U17.24 U17.25 U17.26 U17.27 U17.30 U17.31 U17.36 U19.8 U20.8 | length 6.8
  Top Layer w0.381: v1@182.84,77.074 U17.36@183.676,77.074
  Top Layer w0.5: C163.1@174.851,79.057 174.851,78.27 U20.8@174.859,78.262 ; v1(182.838,77.072) v1@182.84,77.074 ; U19.8@199.8,77.011 199.8,78.529 200.561,79.29 C150.2@201.215,79.29 ; C147.2@207.979,79.29 208.98,79.29 v1(209,79.271) ; C149.1@208.394,80.486 v1(209.3,80.486)
  other v1: 195.5,76.634 197.2,76.634 198.1,77.034 196.3,77.134 195.5,77.534 197.2,77.534 198.1,77.934 196.3,78.034 197.2,78.518 190.84,78.54 191.737,78.541 192.636,78.541 193.55,78.534 194.472,78.541 195.386,78.534 191.3,79.362 192.186,79.362 193.1,79.362 194.022,79.362 194.936,79.362 195.9,79.358 191.8,80.171 192.686,80.171 193.6,80.171 194.522,80.171 195.436,80.171 187.242,81.234 188.111,81.234 174.2,81.268 208.381,81.529 174.904,82.034 187.242,82.04 188.1,82.04 173.821,82.136
-4V_VDC-1: C178.1 C179.2 C181.2 C187.2 C188.1 C189.1 C190.2 NT19.1 R189.1 R560.1 TP45.1 U23.19 U23.20 U23.21 U23.22 U23.23 U23.24 U23.25 U23.26 U23.27 U23.30 U23.31 U23.36 U25.8 | length 17.4
  Top Layer w0.305: U23.36@232.257,312.215 v1(232.931,312.215)
  Top Layer w0.5: v1(206.95,310.096) 206.974,310.072 C187.2@207.971,310.072 ; C188.1@215.166,308.449 214.668,308.947 C190.2@214.668,310.096 215.338,310.096 216.15,310.908 U25.8@216.15,312.358 ; C181.2@232.8,303.9 234.068,303.9 R189.1@234.7,304.532 234.7,310.446 v1(232.931,312.215)
  other v1: 227.79,307.2 228.684,307.2 207.496,307.88 217.39,307.942 216.571,308.768 206.65,308.88 220.501,309.141 221.415,309.141 222.337,309.141 223.251,309.141 224.137,309.141 220.037,309.955 221.001,309.951 221.915,309.951 222.837,309.951 223.751,309.951 224.637,309.951 220.551,310.778 221.465,310.771 222.387,310.778 223.301,310.771 224.2,310.771 225.096,310.772 218.737,310.795 219.637,311.278 217.837,311.378 218.737,311.778 220.437,311.778 219.637,312.178 217.837,312.278 218.737,312.678 220.437,312.678
  other v2: 227.79,308 228.684,308
-4V_VDC-2: C182.2 C200.2 C202.1 C203.2 C204.1 C416.1 NT25.1 R561.1 TP46.1 U26.8 U57.19 U57.20 U57.21 U57.22 U57.23 U57.24 U57.25 U57.26 U57.27 U57.30 U57.31 U57.36 | length 7.9
  Top Layer w0.5: v1(206.652,217.912) 206.668,217.927 C202.1@207.573,217.927 ; v1(206.952,219.127) 206.972,219.108 C200.2@207.973,219.108 ; C203.2@214.652,219.108 C203.2@214.67,219.108 ; C203.2@214.67,219.127 C203.2@214.67,219.108 ; C204.1@215.168,217.48 215.168,217.944 214.67,218.442 C203.2@214.67,219.108 ; U26.8@216.152,221.39 216.152,219.748 215.512,219.108 C203.2@214.67,219.108 ; U57.36@232.316,221.19 v1(232.99,221.19)
  other v1: 227.838,216.304 228.697,216.304 207.498,216.912 217.392,216.974 216.573,217.8 220.503,218.173 221.417,218.173 222.339,218.173 223.253,218.173 224.139,218.173 220.039,218.986 221.003,218.982 221.917,218.982 222.839,218.982 223.753,218.982 224.639,218.982 221.467,219.803 223.303,219.803 224.202,219.803 225.098,219.804 218.739,219.826 220.553,219.81 222.389,219.81 219.639,220.31 217.839,220.41 218.739,220.81 220.439,220.81 219.639,221.21 217.839,221.31 218.739,221.71 220.439,221.71
  other v2: 227.827,217.11 228.697,217.11
-4V_VDC-3: C193.2 C213.2 C215.1 C216.2 C217.1 C424.1 NT26.1 R562.1 TP49.1 U27.8 U58.19 U58.20 U58.21 U58.22 U58.23 U58.24 U58.25 U58.26 U58.27 U58.30 U58.31 U58.36 | length 8
  Top Layer w0.305: U58.36@232.259,130.251 v1(232.897,130.251)
  Top Layer w0.5: v1(206.652,126.916) 206.668,126.932 C215.1@207.573,126.932 ; v1(206.952,128.132) 206.976,128.109 C213.2@207.973,128.109 ; C217.1@215.168,126.485 214.67,126.984 C216.2@214.67,128.109 215.74,128.109 216.152,128.521 U27.8@216.152,130.394
  other v1: 227.838,125.309 228.697,125.309 207.498,125.916 217.392,125.979 216.573,126.805 220.503,127.178 221.417,127.178 222.339,127.178 223.253,127.178 224.139,127.178 220.039,127.991 221.003,127.987 221.917,127.987 222.839,127.987 223.753,127.987 224.639,127.987 220.553,128.815 221.467,128.808 222.389,128.815 223.303,128.808 224.202,128.808 225.098,128.809 218.739,128.831 219.639,129.315 217.839,129.415 218.739,129.815 220.439,129.815 219.639,130.215 217.839,130.315 218.739,130.715 220.439,130.715
  other v2: 227.827,126.115 228.697,126.115
\DIAG_L1: R132.2 U14.14 | length 5.5
  Top Layer w0.203: v2(6.2,155.832) R132.2@6.2,156.534
  Top Layer w0.229: v2(9.331,156.52) U14.14@10.691,156.52
  Signal Layer 2 w0.229: v2(6.2,155.832) 6.888,156.52 v2(9.331,156.52)
\DIAG_L2: R137.2 U15.14 | length 6.3
  Top Layer w0.229: v2(5.3,124.2) R137.2@6.2,124.2 ; v2(9.331,124.262) U15.14@10.691,124.262
  Signal Layer 2 w0.229: v2(5.3,124.2) 9.269,124.2 v2(9.331,124.262)
\DIAG_L3: R142.2 U16.14 | length 6.2
  Top Layer w0.203: v2(5.381,140.319) 5.412,140.35 R142.2@6.2,140.35
  Top Layer w0.229: v2(9.373,140.335) U16.14@10.733,140.335
  Signal Layer 2 w0.229: v2(5.381,140.319) 5.397,140.335 v2(9.373,140.335)
\EN_DCDC_GATES: R455.1 R464.2 | length 73.3
  Top Layer w0.203: R464.2@59.302,295 59.302,294.491 63.693,290.1 66.5,290.1 70.3,286.3 70.3,274.378 70.866,273.812 v2(76.674,273.812) ; R455.1@105.192,268.728 R455.1@105.192,268.728 105.193,271.309 107.95,274.066 v2(107.95,274.574)
  Bottom Layer w0.203: v2(76.674,273.812) 78.198,272.288 88.333,272.288 90.622,274.578 90.626,274.574 v2(107.95,274.574)
\PG_MID: R249.1 U30.3 | length 3.4
  Top Layer w0.203: U30.3@182.628,322.165 182.628,323.341 182.886,323.598 R249.1@184.715,323.598
\PG_MID2: R267.1 U55.3 | length 3.4
  Top Layer w0.229: U55.3@182.63,231.197 182.73,231.297 182.73,232.594 182.766,232.63 R267.1@184.717,232.63
\PG_MID3: R508.1 U56.3 | length 3.4
  Top Layer w0.229: U56.3@182.63,140.201 182.63,141.349 182.916,141.635 R508.1@184.717,141.635
\PG_SN_L1: R278.1 U36.3 | length 3.5
  Top Layer w0.229: R278.1@183.036,247.536 183.052,247.52 184.974,247.52 U36.3@184.974,249.085
\PG_SN_L2: R317.1 U43.3 | length 3.4
  Top Layer w0.229: R317.1@183.078,156.57 184.785,156.57 185.016,156.8 U43.3@185.016,158.119
\PG_SN_L3: R148.1 U17.3 | length 3.4
  Top Layer w0.229: R148.1@183.038,65.574 184.791,65.574 184.976,65.76 U17.3@184.976,67.124
\PG_UCC_AEF: R104.2 U11.3 | length 3.2
  Top Layer w0.203: U11.3@61.293,164.221 62.95,164.221 63.181,163.99 R104.2@63.181,162.814
\PG_VDC-: R187.1 U23.3 | length 3.2
  Top Layer w0.229: U23.3@230.957,322.165 230.957,323.419 231.144,323.605 R187.1@232.857,323.605
\PG_VDC-2: R528.1 U57.3 | length 3.2
  Top Layer w0.229: U57.3@230.902,231.14 231.002,231.24 231.002,232.455 231.148,232.6 R528.1@232.809,232.6
\PG_VDC-3: R536.1 U58.3 | length 3
  Top Layer w0.229: U58.3@230.959,140.201 230.959,141.211 231.353,141.605 R536.1@232.809,141.605
A033_REF1: C267.1 R207.1 U44.6 | length 2.8
  Top Layer w0.203: U44.6@66.187,94.29 67.89,94.29 C267.1@67.9,94.3 R207.1@69,94.3
A033_REF2: C302.1 R225.1 U49.6 | length 2.8
  Top Layer w0.203: U49.6@69.613,84.356 R225.1@72.456,84.356
A033_REF3: C327.1 R300.1 U59.6 | length 2.8
  Top Layer w0.203: U59.6@73.497,74.516 76.3,74.516 R300.1@76.31,74.525
AEF_CHK_1: C77.2 C83.2 L4.EI R77.I1 | length 24.6
  Top Layer w1: v1(29.027,163.27) 30.406,163.27 44.506,149.17 C83.2@46.356,149.17
  Top Layer w2: 29.056,155.702 C77.2@29.056,157.132
  other v2: 27.929,156.52 30.2,156.57 27.941,157.682 30.2,157.71 28.056,158.529 30.026,158.545 29.056,158.607
AEF_CHK_2: C78.2 C82.2 L4.EII R78.I1 | length 24.9
  Top Layer w1: C82.2@46.356,118.325 v1(48.782,118.325)
  Signal Layer 2 w1: C78.2@29.056,124.985 33.167,124.985 39.827,118.325 v1(48.782,118.325)
  other v1: 40.819,180.882 42.361,180.867 43.9,180.994 41.575,181.5 43.133,181.629 42.272,182.334
  other v2: 27.893,124.206 30.164,124.255 27.906,125.368 30.164,125.396 28.02,126.214 29.991,126.231 29.02,126.292
AEF_CHK_3: C79.2 C81.2 L4.EIII R79.I1 | length 25.1
  Top Layer w1: C81.2@46.356,133.295 46.367,133.305 v1(48.7,133.305)
  Signal Layer 2 w1: C79.2@29.056,140.849 39.062,140.849 46.606,133.305 v1(48.7,133.305)
  other v1: 40.548,159.416 39.548,161.416 36.548,163.416 38.548,163.416 40.548,163.416 35.548,165.416 37.548,165.416 39.548,165.416 36.548,167.416 38.548,167.416 35.548,169.416 37.548,169.416 39.548,169.416 36.548,171.416 38.548,171.416 35.548,173.416 37.548,173.416 39.548,173.416 34.548,175.416 36.548,175.416 38.548,175.416 31.548,177.416 33.548,177.416 35.548,177.416 30.548,179.416 32.548,179.416 34.548,179.416 27.548,181.416 29.548,181.416 31.548,181.416 33.548,181.416 26.548,183.416 28.548,183.416 30.548,183.416 32.548,183.416 23.548,185.416 25.548,185.416 27.548,185.416 29.548,185.416 31.548,185.416 33.548,185.416 22.548,187.416 24.548,187.416 26.548,187.416 28.548,187.416 30.548,187.416 32.548,187.416 19.548,189.416 21.548,189.416 23.548,189.416 25.548,189.416 27.548,189.416 29.548,189.416 18.548,191.416 20.548,191.416 22.548,191.416 24.548,191.416 26.548,191.416 28.548,191.416 17.548,193.416 19.548,193.416 21.548,193.416 23.548,193.416 25.548,193.416 18.548,195.416 20.548,195.416 22.548,195.416 24.548,195.416 17.548,197.416 19.548,197.416 21.548,197.416 18.548,199.416 20.548,199.416 18.622,202.206 19.919,202.65 17.319,202.736 16.822,203.95 20.519,203.95 17.2,205.2 19.996,205.311 18.622,205.85
  other v2: 27.893,139.98 30.164,140.03 27.906,141.143 30.164,141.17 29.857,141.876 28.021,141.989 29.02,142.067
AEF_CHK_N: C77.1 C78.1 C79.1 C80.2 C84.2 | length 58.2
  Top Layer w0.508: C77.1@56.556,157.132 58.099,157.132 58.878,156.353 62.163,156.353 63.347,155.169 C84.2@63.347,154.096
  Bottom Layer w1: C80.2@50.215,112.196 51.393,113.374 54.122,113.374 56.556,115.808 C78.1@56.556,124.985 56.556,128.712 56.162,129.106 56.162,133.343 56.556,133.737 C79.1@56.556,140.849 C77.1@56.556,157.132
AEF_INJ: R66.1 R69.1 U12.13 | length 3.2
  Top Layer w0.254: U12.13@66.365,133.238 67.022,133.238 67.447,133.663 R69.1@67.913,133.663 R66.1@69.418,133.663
AEF_INJ_CM: C7.2 C88.2 C91.2 R64.1 R69.2 | length 7.1
  Top Layer w0.254: C91.2@66.581,135.846 66.581,136.215 66.798,136.432 C88.2@68.075,136.432 67.913,136.27 R69.2@67.913,134.863
  Top Layer w0.305: R64.1@66.25,138.237 67.902,138.237 67.902,136.605 C88.2@68.075,136.432
AEF_SENS1: C83.1 U12.4 | length 23.5
  Top Layer w0.254: C83.1@56.556,149.17 58.951,149.17 v2(61.163,146.958) ; v2(60.867,131.8) 61.304,132.238 U12.4@63.365,132.238
  Signal Layer 2 w0.254: v2(60.867,131.8) 60.867,145.96 61.163,146.257 v2(61.163,146.958)
AEF_SENS2: C82.1 U12.5 | length 18.5
  Top Layer w0.254: C82.1@56.556,118.325 59.357,118.325 v2(61.802,120.771) ; v2(61.802,129) 61.802,131.311 62.209,131.718 63.345,131.718 U12.5@63.365,131.738
  Signal Layer 2 w0.254: v2(61.802,120.771) v2(61.802,129)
